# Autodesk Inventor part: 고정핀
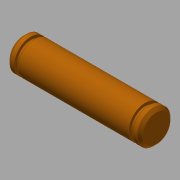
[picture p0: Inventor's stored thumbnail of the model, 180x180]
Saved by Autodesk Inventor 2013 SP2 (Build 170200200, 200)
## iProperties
Created: 2015-12
Part Number: 고정핀
Material: 스테인리스강
Document SubType Name: Modeling
Designer: mduedu
Density: 8.08 g/cm^3
Author: mduedu
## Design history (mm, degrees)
sketch "스케치1"
  geometry: C1 r 3 at (0, 0); 1 further point
  constraints: 1 centre point, 1 coincident
  dimensions: "d0" = 6 diameter of C1
extrude "돌출1" new body sketch "스케치1" stored distance "d1" = 24; taper "d2" = 0 deg
chamfer "모따기1" distance "d3" = 0.5; stored, may be unused: second distance "d4" = 2, angle "d5" = 45 deg
sketch "스케치2"
  geometry: L1 (-12, 2.5)-(-11.5, 3) reference; L2 (-11.5, 3)-(11.5, 3) reference; L3 (11.5, 3)-(12, 2.5) reference; L4 (12, 2.5)-(12, -2.5) reference; L5 (12, -2.5)-(11.5, -3) reference; L6 (11.5, -3)-(-11.5, -3) reference; L7 (-11.5, -3)-(-12, -2.5) reference; L8 (-12, -2.5)-(-12, 2.5) reference; L9 (10, 3)-(10.7, 3); L10 (10.7, 3)-(10.7, 2.5); L11 (10.7, 2.5)-(10, 2.5); L12 (10, 2.5)-(10, 3); L13 (0, 0)-(12, 0)
  constraints: 10 end point, 2 parallel, 1 collinear, 1 horizontal, 1 midpoint, 1 perpendicular
  dimensions: "d6" = 10 distance from line of L12 L13.start; "d7" = 5 diameter of L11 L13; "d8" = 0.7 distance of L9.start L9.end
revolve "회전1" sketch "스케치2" stored, may be unused: angle "d9" = 90 deg
node "솔리드1"
mirror "대칭1"
node "절단 모서리 투영1"
